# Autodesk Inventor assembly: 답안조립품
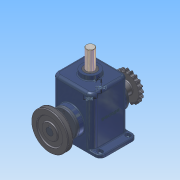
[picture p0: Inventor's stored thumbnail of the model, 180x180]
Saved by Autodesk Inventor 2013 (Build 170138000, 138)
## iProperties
Created: 2015-03
Part Number: 답안조립품
Document SubType Name: Assembly
Designer: Administrator
Author: Administrator
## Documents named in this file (15)
- C:\Documents and Settings\Administrator\바탕 화면\350305V1013\답안조립품.iam
- C:\Documents and Settings\Administrator\바탕 화면\350305V1013\본체.ipt
- C:\Documents and Settings\Administrator\바탕 화면\350305V1013\베어링 6205.ipt
- C:\Documents and Settings\Administrator\바탕 화면\350305V1013\편심축.ipt
- C:\Documents and Settings\Administrator\바탕 화면\350305V1013\커버.ipt
- C:\Documents and Settings\Administrator\바탕 화면\350305V1013\M4x0.5.ipt
- C:\Documents and Settings\Administrator\바탕 화면\350305V1013\오일실.ipt
- C:\Documents and Settings\Administrator\바탕 화면\350305V1013\키 8x8.ipt
- C:\Documents and Settings\Administrator\바탕 화면\350305V1013\체인 스프로킷.ipt
- C:\Documents and Settings\Administrator\바탕 화면\350305V1013\멈춤나사 M5x0.5.ipt
- C:\Documents and Settings\Administrator\바탕 화면\350305V1013\멈춤링.ipt
- C:\Documents and Settings\Administrator\바탕 화면\350305V1013\V-벨트풀리.ipt
- C:\Documents and Settings\Administrator\바탕 화면\350305V1013\부시.ipt
- C:\Documents and Settings\Administrator\바탕 화면\350305V1013\슬라이드.ipt
- C:\Documents and Settings\Administrator\바탕 화면\350305V1013\가변스프링.ipt
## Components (9 placed, 4 different names)
1. 5-체인 스프로킷:1 — 플러쉬:2, 각도:2
2. V-벨트풀리:1 — 플러쉬:4, 각도:4
3. 가변스프링:1
4. M4x0.5:1
5. M4x0.5:2
6. M4x0.5:3
7. M4x0.5:4
8. M4x0.5:5
9. M4x0.5:6
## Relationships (4: Flush 2, Angle 2)
- 플러쉬:2 [Flush]: 5-체인 스프로킷:1
- 각도:2 [Angle]: 5-체인 스프로킷:1
- 플러쉬:4 [Flush]: V-벨트풀리:1
- 각도:4 [Angle]: V-벨트풀리:1
